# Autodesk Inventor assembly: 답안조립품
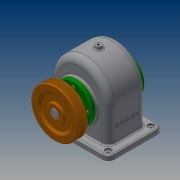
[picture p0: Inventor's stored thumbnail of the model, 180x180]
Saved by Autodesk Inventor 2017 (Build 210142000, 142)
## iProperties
Part Number: 답안조립품
Material: 일반
Document SubType Name: Assembly
Designer: 20
Author: 20
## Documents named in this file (14)
- C:\Users\20\Desktop\480310V1001\답안조립품.iam
- C:\Users\20\Desktop\480310V1001\본체.ipt
- C:\Users\20\Desktop\480310V1001\앞커버.ipt
- C:\Users\20\Desktop\480310V1001\뒤커버.ipt
- C:\Users\20\Desktop\480310V1001\축.ipt
- C:\Users\20\Desktop\480310V1001\베어링 6203.ipt
- C:\Users\20\Desktop\480310V1001\부시.ipt
- C:\Users\20\Desktop\480310V1001\오일 실 28 40 8.ipt
- C:\Users\20\Desktop\480310V1001\키 5x5x18.ipt
- C:\Users\20\Desktop\480310V1001\키 6x6x22.ipt
- C:\Users\20\Desktop\480310V1001\스퍼기어.ipt
- C:\Users\20\Desktop\480310V1001\V-벨트풀리.ipt
- C:\Users\20\Desktop\480310V1001\멈춤나사 M4.ipt
- C:\Users\20\Desktop\480310V1001\볼트 M4.ipt
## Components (1 placed, 1 different names)
1. V-벨트풀리:1 — 플러쉬:1
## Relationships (1: Flush 1)
- 플러쉬:1 [Flush]: V-벨트풀리:1
